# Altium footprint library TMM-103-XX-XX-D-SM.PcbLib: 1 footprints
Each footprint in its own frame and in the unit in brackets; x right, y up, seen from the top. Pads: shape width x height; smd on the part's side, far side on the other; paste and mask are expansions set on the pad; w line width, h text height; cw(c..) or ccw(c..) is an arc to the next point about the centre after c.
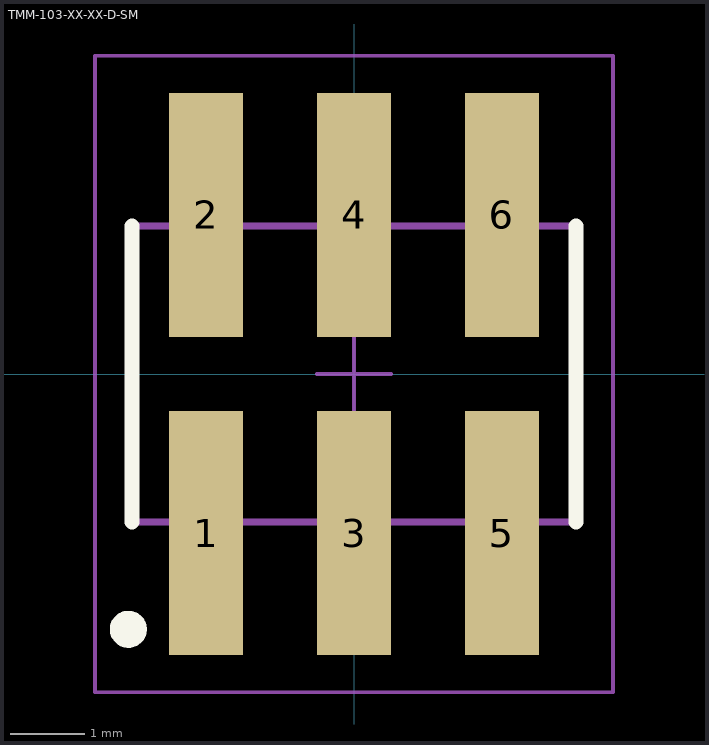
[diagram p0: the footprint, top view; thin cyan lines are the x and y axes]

## TMM-103-XX-XX-D-SM [mm] "2.00mm pitch, 6 pin, terminal strip; double row, SMT"
height 2.77
pads (6):
  rect 1x3.3 smd mask+0: 1(-2,-2.15) 2(-2,2.15) 3(0,-2.15) 4(0,2.15) 5(2,-2.15) 6(2,2.15)
Top Overlay:
  circle w0.25: c-3.05,-3.45 r0.125
  lines w0.2: -3,-2 -3,2 ; 3,-2 3,2
Mechanical 12:
  lines w0.001: -3,-2 -3,2 3,2 3,-2 -3,-2
Mechanical 13:
  lines w0.1: -3,-2 -3,2 3,2 3,-2 -3,-2
  text ".Designator" at 0,-0.127 h1.52
Mechanical 15:
  lines w0.05: -0.5,0 0.5,0 ; 0,-0.5 0,0.5 ; -3.5,-4.3 -3.5,4.3 3.5,4.3 3.5,-4.3 -3.5,-4.3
